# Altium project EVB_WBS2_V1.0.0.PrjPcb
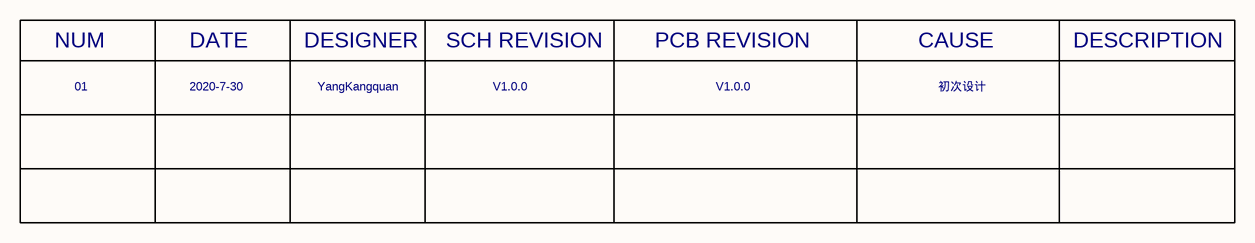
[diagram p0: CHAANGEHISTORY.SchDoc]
3 sheets, 28 parts. Net scope: global (net labels, ports and power ports of the same name join across sheets).
Sheets:
  CHAANGEHISTORY.SchDoc
  BLOCK_DIAGRAM.SchDoc
  ATBM6031.SchDoc

## Sheet CHAANGEHISTORY.SchDoc: EVB_WBS2_V1.0.0
size A4; Revision: V1.0.0; SheetNumber: 1; SheetTotal: 3

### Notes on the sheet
- NUM
- DATE
- DESIGNER
- SCH REVISION
- PCB REVISION
- CAUSE
- DESCRIPTION
- 01
- 2020-7-30
- YangKangquan
- V1.0.0
- 初次设计

## Sheet BLOCK_DIAGRAM.SchDoc: EVB_WBS2_V1.0.0
size A4; Revision: V1.0.0; SheetNumber: 2; SheetTotal: 3
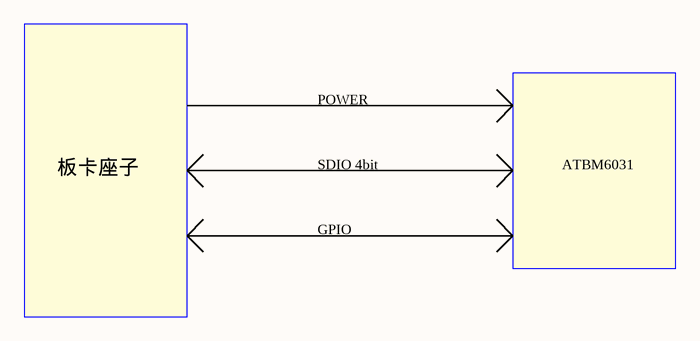
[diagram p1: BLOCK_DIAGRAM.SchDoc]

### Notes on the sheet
- POWER
- 板卡座子
- SDIO 4bit
- ATBM6031
- GPIO

## Sheet ATBM6031.SchDoc: EVB_WBS2_V1.0.0
size A4; Revision: V1.0.0; SheetNumber: 3; SheetTotal: 3
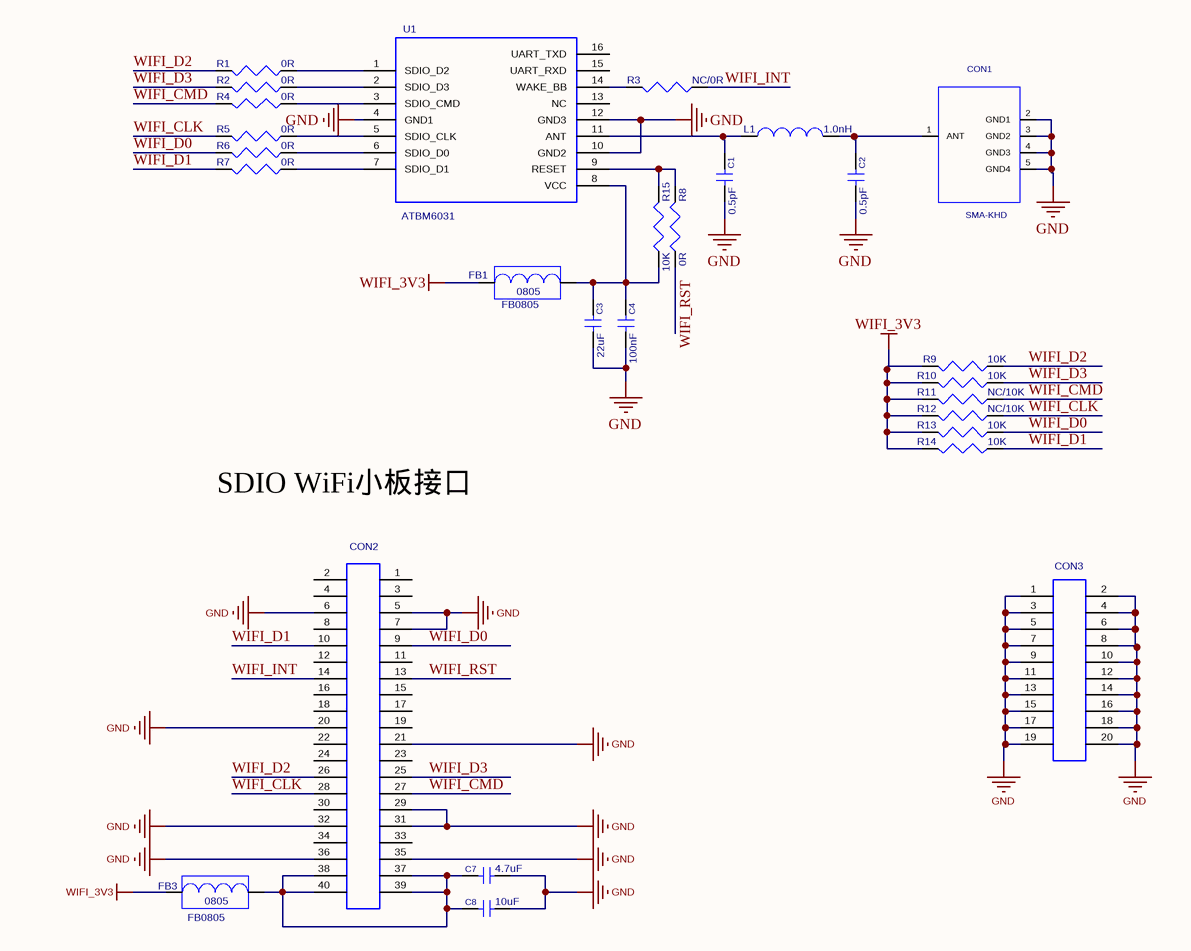
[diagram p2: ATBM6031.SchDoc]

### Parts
C1  0.5pF  [C0402]
C2  0.5pF  [C0402]
C3  22uF  [C0603]
C4  100nF  [C0603]
C7  4.7uF  [C0603]
C8  10uF  [C0603]
CON1  value SMA-KHD  [SMA-KHD-92105001]  (hidden comment: SMA-KHD-92105001)
CON2  CON20X2_0MM5_BTB_DF12  [CON20X2_0MM5_BTB_DF12_N]  (value not drawn)
CON3  CON10X2_0MM5_BTB_DF12  [CON10X2_0MM5_BTB_DF12_N]  (value not drawn)
FB1  FB0805  [FB0805]
FB3  FB0805  [FB0805]
L1  1.0nH  [L0402]
R1  0R  [R0603]
R2  0R  [R0603]
R3  NC/0R  [R0603]
R4  0R  [R0603]
R5  0R  [R0603]
R6  0R  [R0603]
R7  0R  [R0603]
R8  0R  [R0603]
R9  10K  [R0603]
R10  10K  [R0603]
R11  NC/10K  [R0603]
R12  NC/10K  [R0603]
R13  10K  [R0603]
R14  10K  [R0603]
R15  10K  [R0603]
U1  ATBM6031  [ATBM6031]

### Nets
GND: C1.2 C2.2 C3.2 C4.2 C7.2 C8.2 CON1.2(GND1) CON1.3(GND2) CON1.4(GND3) CON1.5(GND4) CON2.5 CON2.6 CON2.7 CON2.20 CON2.21 CON2.29 CON2.31 CON2.32 CON2.35 CON2.36 CON3.1 CON3.2 CON3.3 CON3.4 CON3.5 CON3.6 CON3.7 CON3.8 CON3.9 CON3.10 CON3.11 CON3.12 CON3.13 CON3.14 CON3.15 CON3.16 CON3.17 CON3.18 CON3.19 CON3.20 U1.4(GND1) U1.10(GND2) U1.12(GND3)
WIFI_3V3: FB1.1 FB3.1 R9.2 R10.2 R11.2 R12.2 R13.2 R14.2
WIFI_CLK: CON2.28 R5.2 R12.1
WIFI_CMD: CON2.27 R4.2 R11.1
WIFI_D0: CON2.9 R6.2 R13.1
WIFI_D1: CON2.10 R7.2 R14.1
WIFI_D2: CON2.26 R1.2 R9.1
WIFI_D3: CON2.25 R2.2 R10.1
WIFI_INT: CON2.14 R3.1
WIFI_RST: CON2.13 R8.1
NetC1_1: C1.1 L1.1 U1.11(ANT)
NetC2_1: C2.1 CON1.1(ANT) L1.2
NetC3_1: C3.1 C4.1 FB1.2 R15.1 U1.8(VCC)
NetC7_1: C7.1 C8.1 CON2.37 CON2.38 CON2.39 CON2.40 FB3.2
NetR1_1: R1.1 U1.1(SDIO_D2)
NetR2_1: R2.1 U1.2(SDIO_D3)
NetR3_2: R3.2 U1.14(WAKE_BB)
NetR4_1: R4.1 U1.3(SDIO_CMD)
NetR5_1: R5.1 U1.5(SDIO_CLK)
NetR6_1: R6.1 U1.6(SDIO_D0)
NetR7_1: R7.1 U1.7(SDIO_D1)
NetR8_2: R8.2 R15.2 U1.9(RESET)

Not connected (* = marked no-connect by the designer): CON2 1 2 3 4 8 11 12 15 16 17 18 19 22 23 24 30 33 34; U1 13(NC) 15(UART_RXD) 16(UART_TXD)

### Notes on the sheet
- SDIO WiFi小板接口

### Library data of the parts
C1 C2 = CC0200R52XX: C/C,0.5pF,50V,±0.05pF ,0402,Murata; Catalog: 陶瓷电容
C3 = CC0302260XX: C/C,22uF,16V,+/-20%,0603; Catalog: 陶瓷电容
C4 = CC0301040XX: C/C,100nF,25V,+/-5%,0603; Catalog: 陶瓷电容
C7 = CC0304750XX: C/C,4.7uF,25V,+/-5%,0603; Catalog: 陶瓷电容
C8 = CC0301060XX: C/C,10uF,25V,+/-5%,0603; Catalog: 陶瓷电容
CON1 = CNRFM0515XX: SMA-KWE,5pin,Normal，弯头正脚内孔，6*6*13&14.5；; Part Number_AK: CNRFM0501XX; Source_Path: I:\PROJECTFILES\CADENCE\AD11\AD11_AK9806_V2.1_20120202.DSN; Catalog: Connector
CON2 = CNBBM4000XX: 0.5mm ，BTB2*20Pin，SMT，公座，H3.0，DF12#(3.0)-40DS-0.5; PCB DECAL: CON20X2_0MM5_BTB_DF12_BOTTOM; Catalog: Connector
CON3 = CNBBM2000XX: 0.5mm ，BTB2*10Pin，SMT，公座，H3.0，DF12#(3.0)-20DS-0.5; PCB DECAL: CON10X2_0MM5_BTB_DF12_BOTTOM; Catalog: Connector
FB1 FB3 = BE0503010XX: BEAD,PZ2012U301-1R5TF,300R,100MHz,0805; Catalog: 贴片磁珠
L1 = CL0201R00XX: C/L,1.0nH,0402,LQG15HS1N0S02D; Catalog: 贴片电感
R1-R8 = CR0300000XX: Res,0R,1/10W,+/-5%,0603; Catalog: 贴片电阻
R9-R15 = CR0310020XX: Res,10K,1/10W,+/-1%,0603; Catalog: 贴片电阻
U1 = MDWIFI035XX: SDIO2.0 WIFI Module,WD_ATBM6031,13.5 *13*1.6mm, ATBM6031,13pin; Part Number_AK: MDWIFI011XX; Value: NC/R8782; PCB DECAL: BL_R8801MS1; Catalog: 模块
